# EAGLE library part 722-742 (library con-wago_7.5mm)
Serie 722, Federleiste mit geraden Einlötstiften / Series 722, Female connector with straight solder pins Polzahl / Pole No.: 12 Rastermaß / Pitch: 7.5 mm Bemessungsspannung / Rated Voltage: 630 V Nennstrom / Nominal Current: 12 A Lötstiftlänge: / Solder Pin Length: 5 mm Farbe / Color: lichtgrau / light gray Stand: 01.01.2012. Die jeweils aktuellen Daten zu diesem Artikel finden Sie in unserem Produktkatalog, den Sie unter www.wago.com einsehen können. As of: 01/01/2012. Please find the newest data for this article in our product catalogue, which can be viewed under www.wago.com.
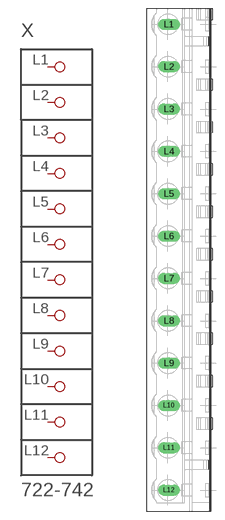
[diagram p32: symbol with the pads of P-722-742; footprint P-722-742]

Designator prefix X

## 722-742  [P-722-742]
L1  P1
L2  P2
L3  P3
L4  P4
L5  P5
L6  P6
L7  P7
L8  P8
L9  P9
L10  P10
L11  P11
L12  P12

## Footprint P-722-742 (pad centres in mm)
drill 1.3 long: L1 -2.203,41.7; L2 -2.203,34.2; L3 -2.203,26.7; L4 -2.203,19.2; L5 -2.203,11.7; L6 -2.203,4.2; L7 -2.203,-3.3; L8 -2.203,-10.8; L9 -2.203,-18.3; L10 -2.203,-25.8; L11 -2.203,-33.3; L12 -2.203,-40.8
